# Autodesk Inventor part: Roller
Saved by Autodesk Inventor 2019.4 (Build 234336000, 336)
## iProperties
Created: 2020-06
Part Number: Roller
Material: Generic
Document SubType Name: Modeling
Designer: Administrator
Density: 1 g/cm^3
Appearance: Default
Title: Roller v3
Author: Administrator
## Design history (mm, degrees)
feature "Body1"
feature "Body2"
feature "Body4"
body "Solid1"
body "Solid2"
body "Solid3"
